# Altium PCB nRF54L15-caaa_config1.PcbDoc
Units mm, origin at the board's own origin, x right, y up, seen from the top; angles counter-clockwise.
Board outline 10.87 x 7.5 mm, 8 copper layers (Top Layer, Mid-Layer 1, Mid-Layer 2, Mid-Layer 3, Mid-Layer 4, Mid-Layer 5, Mid-Layer 6, Bottom Layer), stack 1.547 mm thick; 17 components, 46 nets, 81 pads, 107 vias.
Unrouted connection lines stored in the file: 18.
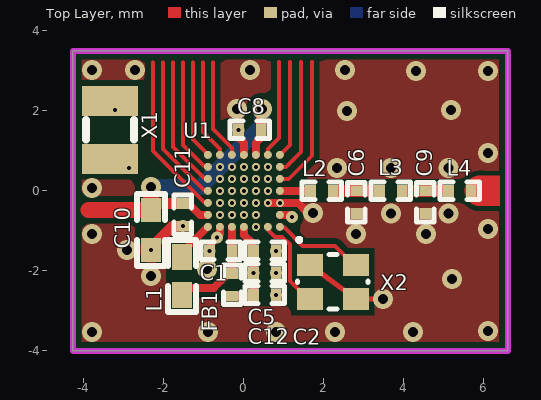
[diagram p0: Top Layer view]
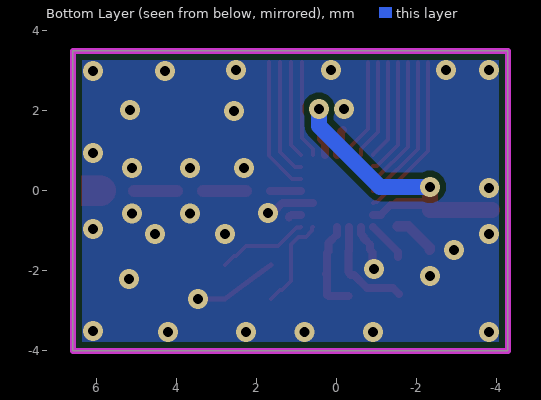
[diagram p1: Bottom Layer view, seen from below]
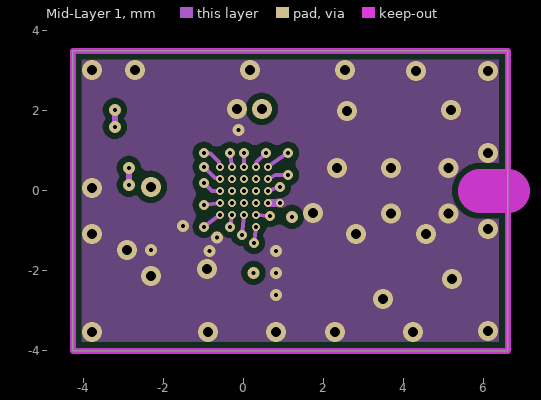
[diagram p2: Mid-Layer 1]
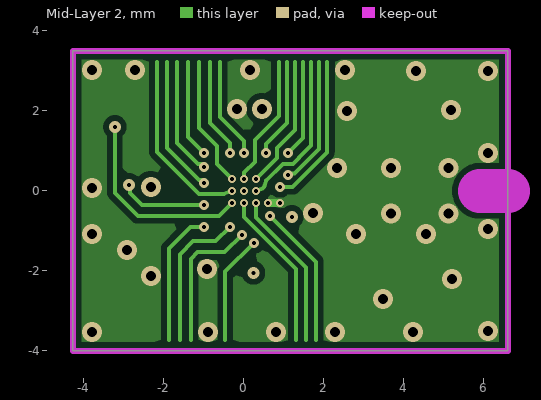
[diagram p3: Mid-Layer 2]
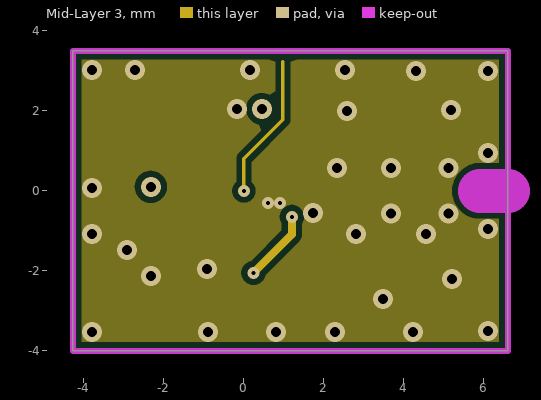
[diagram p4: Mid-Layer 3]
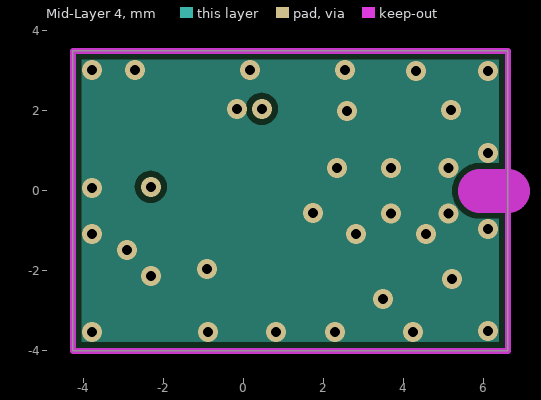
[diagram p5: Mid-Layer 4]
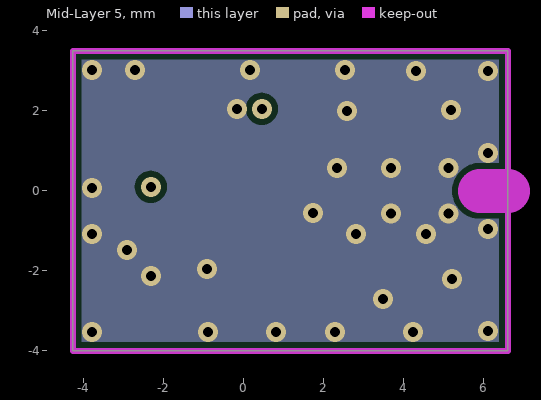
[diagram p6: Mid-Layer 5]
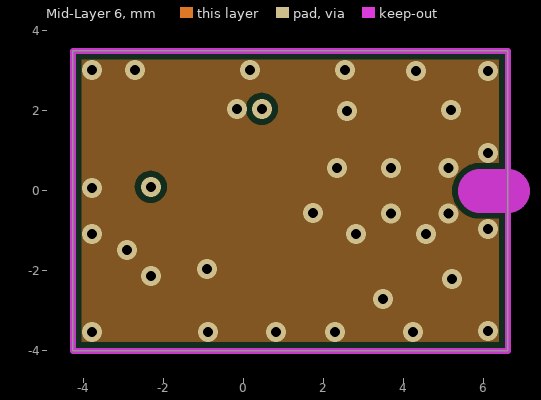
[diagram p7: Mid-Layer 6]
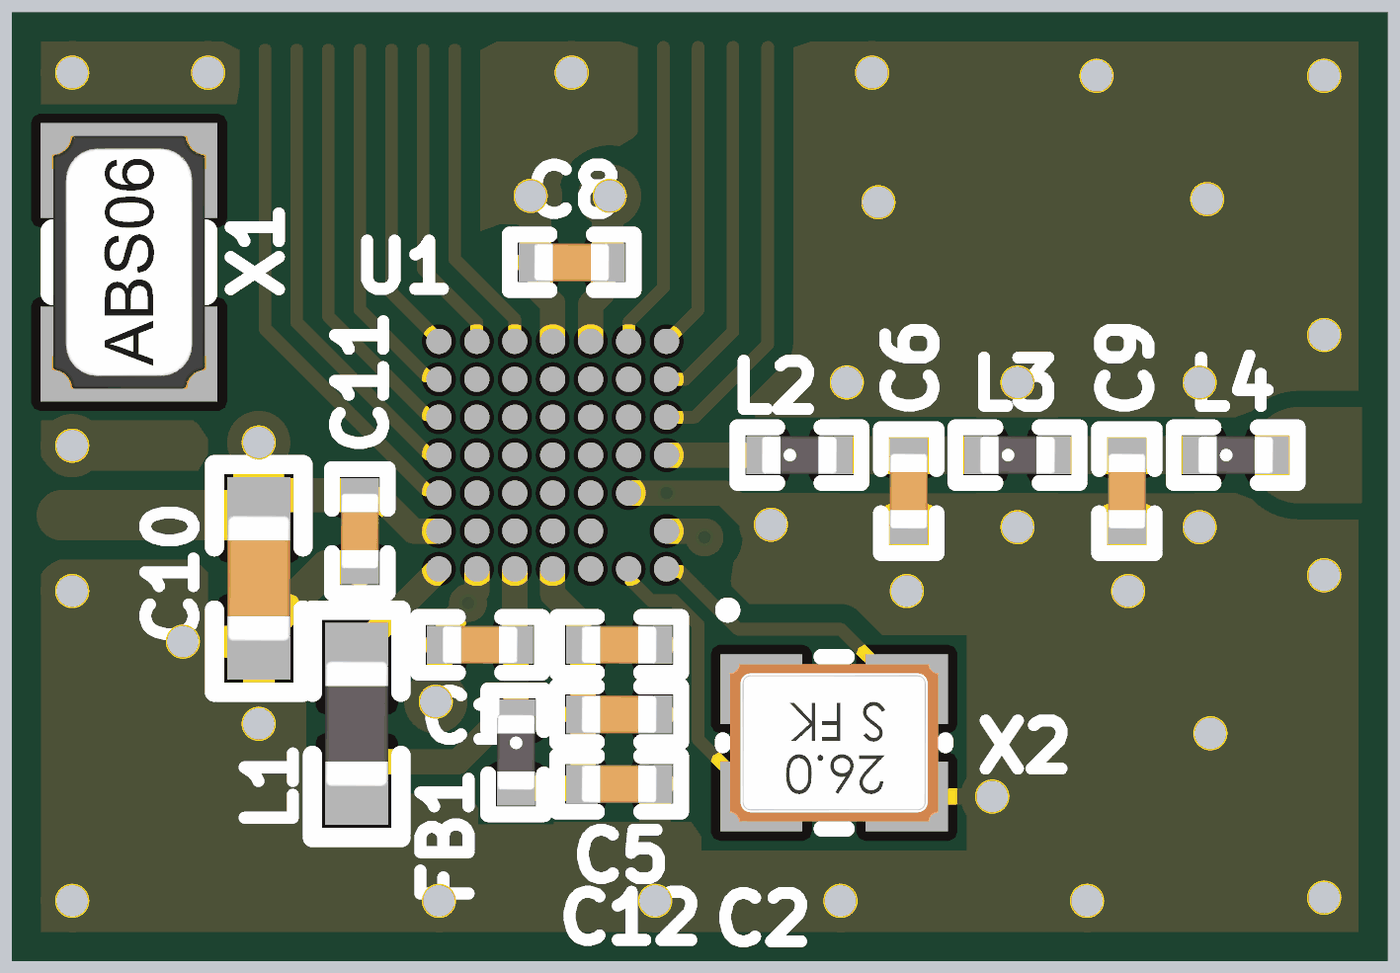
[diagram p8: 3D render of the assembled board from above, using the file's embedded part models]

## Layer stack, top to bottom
Top Solder: solder mask 0.011, Solder Resist, Dk 3.5
Top Layer: signal copper 0.035
Dielectric 1: prepreg 0.08, Dk 4.2
Mid-Layer 1: signal copper 0.035
Dielectric 2: prepreg 0.08, Dk 4.1
Mid-Layer 2: signal copper 0.035
Dielectric 6: prepreg 0.08, Dk 4.1
Mid-Layer 3: signal copper 0.035
Dielectric 3: core 0.7874, Dk 4.6
Mid-Layer 4: signal copper 0.035
Dielectric 7: prepreg 0.08, Dk 4.1
Mid-Layer 5: signal copper 0.035
Dielectric 4: prepreg 0.08, Dk 4.1
Mid-Layer 6: signal copper 0.035
Dielectric 5: prepreg 0.08, Dk 4.2
Bottom Layer: signal copper 0.035
Board Layer Stack Bottom Solder: solder mask 0.011, Solder Resist, Dk 3.5

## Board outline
-4.275,-4 6.6,-4 6.6,3.5 -4.275,3.5

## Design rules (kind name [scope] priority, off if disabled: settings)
Clearance Polygon_ANT [(InNamedPolygon('GND')) or (InNamedPolygon('Bottom_Layer-GND')) or IsRegion vs InNet('RF')] p1: gap=0.127 ignorepadtopadclearanceinfootprint=FALSE
Clearance Clearance_Poly [IsRegion] p2: gap=0.15 ignorepadtopadclearanceinfootprint=FALSE
Clearance [All] p3: gap=0.1 ignorepadtopadclearanceinfootprint=FALSE
ComponentClearance [All] p1 off: gap=0.254 collisioncheckmode=3 verticalgap=0.254 showdistances=FALSE
FabricationTestPointUsage TestPointUsage [All] p1: valid=0 allowmultiple=FALSE
FabricationTestpoint Testpoint [All] p1: side=3 testpointundercomponent=TRUE minsize=1.016 maxsize=2.54 preferedsize=1.524 minholesize=0 maxholesize=1.016 preferedholesize=0.813 testpointgrid=0.025 allowsidetop=TRUE allowsidebottom=TRUE usegrid=TRUE gridtolerance=0
Height [All] p1 off: minheight=0 maxheight=25.4 prefheight=12.7
HoleSize [All] p1: absolutevalues=TRUE maxlimit=4 minlimit=0.1 maxpercent=80.000 minpercent=20.000
HoleToHoleClearance [IsThruVia vs IsThruVia] p1: gap=0.36 allowstackedmicrovias=TRUE
MinimumAnnularRing [All] p1 off: minimumring=0.152
PlaneClearance [All] p1: clearance=0.2
PolygonConnect PolygonConnect_1 [isVia and innet(gnd) or InComponent('C6') or InComponent('C9')] p1: connectstyle=Direct reliefconductorwidth=0.254 reliefentries=4 polygonreliefangle="90 Angle" airgapwidth=0.254
PolygonConnect [All] p2: thpad.connectstyle=Relief thpad.reliefconductorwidth=0.254 thpad.reliefentries=4 thpad.polygonreliefangle="90 Angle" thpad.airgapwidth=0.15 smdpad.connectstyle=Relief smdpad.reliefconductorwidth=0.25 smdpad.reliefentries=4 smdpad.polygonreliefangle="90 Angle" smdpad.airgapwidth=0.15 via.connectstyle=Direct via.reliefconductorwidth=0.254 via.reliefentries=4 via.polygonreliefangle="90 Angle" via.airgapwidth=0.25
RoutingVias [All] p1: holewidth=0.2 width=0.4 viastyle="Through Hole" minholewidth=0.1 minwidth=0.2 maxholewidth=1 maxwidth=2
SilkToSolderMaskClearance SilkscreenOverComponentPads [IsPad] p1: minsilkscreentomaskgap=0.254 clearancetoexposedcopper=TRUE
SolderMaskExpansion SolderMaskExpansion_via [IsVia] p1: expansion=0.102 istentingtop=TRUE
SolderMaskExpansion [All] p2: expansion=0.076 istentingtop=FALSE
SupplyNets "Schematic Supply Nets_1" [InNet('GND')] p1: voltage=0.000
SupplyNets "Schematic Supply Nets" [InNet('VDD_nRF')] p2: voltage=0.000
Width [All] p1: maxlimit=3 minlimit=0.09 preferedwidth=0.15
22 further rules are at their usual default settings.

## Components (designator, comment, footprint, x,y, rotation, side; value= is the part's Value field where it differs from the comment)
C1 "2.2µF" CAPC0603X03L_C -0.575,-1.5 r0 top
C2 "2.2µF" CAPC0603X03L_C 0.525,-2.6 r180 top
C5 "3.9pF" CAPC0603X03L_C 0.525,-1.5 r180 top
C6 "1.7pF" CAPC0603X03L_C 2.815,-0.285 r90 top
C8 "100nF" CAPC0603X03L_C 0.15,1.525 r180 top
C9 "2.0pF" CAPC0603X03L_C 4.54,-0.285 r90 top
C10 "10µF" CAPC1005X04L -2.325,-0.975 r90 top
C11 "100nF" CAPC0603X03L_C -1.525,-0.6 r270 top
C12 "10nF" CAPC0603X03L_C 0.525,-2.05 r180 top
FB1 "120R/0.2A" INDC0603X03L_C -0.29,-2.35 r270 top
L1 "4.7µH" INDC1005X04L -1.55,-2.125 r270 top
L2 "3.6nH" INDC0603X03L_C 1.95,0 r0 top
L3 "4.5nH" INDC0603X03L_C 3.675,0 r0 top
L4 "4.5nH" INDC0603X03L_C 5.4,0 r0 top
U1 "nRF54L15-CAAABB0" BGA49C30P7x7_2245X2451X48 0.084,0 r180 top locked
X1 "32.768kHz" XTAL_2012 -3.35,1.525 r90 top
X2 "32MHz" BT-XTAL_1612 2.225,-2.275 r180 top

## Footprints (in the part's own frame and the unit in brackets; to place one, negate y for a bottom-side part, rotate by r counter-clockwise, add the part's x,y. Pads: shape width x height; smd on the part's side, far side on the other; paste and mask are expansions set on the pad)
BGA49C30P7x7_2245X2451X48 [mm] "BGA/CSP, 47-Leads, Body 0.42x2.451mmx2.245mm, Pitch 0.30mm"
  round 0.2 smd mask+0.035: A1(-0.816,0.9) A2(-0.516,0.9) A3(-0.216,0.9) A4(0.084,0.9) A5(0.384,0.9) A6(0.684,0.9) A7(0.984,0.9) B1(-0.816,0.6) B3(-0.216,0.6) B4(0.084,0.6) B5(0.384,0.6) B6(0.684,0.6) B7(0.984,0.6) C2(-0.516,0.3) C3(-0.216,0.3) C4(0.084,0.3) C5(0.384,0.3) C6(0.684,0.3) C7(0.984,0.3) D1(-0.816,0) D2(-0.516,0) D3(-0.216,0) D4(0.084,0) D5(0.384,0) D6(0.684,0) D7(0.984,0) E1(-0.816,-0.3) E2(-0.516,-0.3) E3(-0.216,-0.3) E4(0.084,-0.3) E5(0.384,-0.3) E6(0.684,-0.3) E7(0.984,-0.3) F1(-0.816,-0.6) F2(-0.516,-0.6) F3(-0.216,-0.6) F4(0.084,-0.6) F5(0.384,-0.6) F6(0.684,-0.6) F7(0.984,-0.6) G1(-0.816,-0.9) G2(-0.516,-0.9) G3(-0.216,-0.9) G4(0.084,-0.9) G5(0.384,-0.9) G6(0.684,-0.9) G7(0.984,-0.9)
  silkscreen extent -1.35,1.18 -1.25,1.27, body extent -1.23,-1.12 1.22,1.12, height 0.42
BT-XTAL_1612 [mm] "Crystal 1.6 x 1.2 mm"
  rect 0.65x0.55 smd: 1(-0.575,-0.425) 2(0.575,-0.425) 3(0.575,0.425) 4(-0.575,0.425)
  silkscreen extent -0.88,-0.68 0.88,0.68, body extent -0.83,-0.63 0.83,0.63, height 0.41
CAPC0603X03L_C [mm] "Chip Capacitor, 2-Leads, Body 0.6x0.3mm, IPC High Density"
  rect 0.27x0.3 smd mask+0.05: 1(-0.285,0) 2(0.285,0)
  silkscreen extent -0.49,-0.22 0.49,0.22, body extent -0.3,-0.15 0.3,0.15, height 0.3
CAPC1005X04L [mm] "Chip Capacitor, 2-Leads, Body 1.0x0.5mm, IPC High Density"
  rect 0.6x0.5 smd: 1(-0.5,0) 2(0.5,0)
  silkscreen extent -0.9,-0.35 0.9,0.35, body extent -0.5,-0.25 0.5,0.25, height 0.5
INDC0603X03L_C [mm] "Chip Inductor, 2-Leads, Body 0.6x0.3mm, IPC High Density"
  rect 0.27x0.3 smd: 1(-0.285,0) 2(0.285,0)
  silkscreen extent -0.49,-0.22 0.49,0.22, body extent -0.3,-0.15 0.3,0.15, height 0.3
INDC1005X04L [mm] "Chip Inductor, 2-Leads, Body 1.0x0.5mm, IPC High Density"
  rect 0.65x0.5 smd: 1(-0.475,0) 2(0.475,0)
  silkscreen extent -0.9,-0.35 0.9,0.35, body extent -0.5,-0.25 0.5,0.25, height 0.5
XTAL_2012 [mm] "XTAL SMD 2.0 x 1.2 mm"
  rect 0.75x1.4 smd: 1(-0.725,0) 2(0.725,0)
  silkscreen extent -0.24,-0.6 0.24,0.6, body extent -1,-0.61 1,0.61, height 0.6

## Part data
C1 C2: library part C0201-2µ2-2.5V-X6T-GRM033D80E225ME47D, "Capacitor, Ceramic, 2.2µF 2.5V X6T 0201,±20%", Manufacturer=Murata, Manufacturer Part Number=GRM033R61A225KE47, Part number IPS=N.A., Part number NEMS=100200527, Supplier Part Number 1=81-GRM033D80E225ME7D
C5: library part C0201-3.9p-HQ-Murata, "Capacitor, NP0, ±0.05pF, 25V", Manufacturer=Murata, Manufacturer Part Number=GJM0333C1E3R9WB01, Part number IPS=N.A., Part number NEMS=100200424
C6: library part C0201-1.7p-25V-NP0-GJM0335C1E1R7WB01, "Capacitor, NP0, ±0.05pF, 25V, High Q", Manufacturer=Murata, Manufacturer Part Number=GJM0335C1E1R7WB01, Part number IPS=N.A., Part number NEMS=100200524, Supplier Part Number 1=GJM0335C1E1R7WB01D-ND
C8 C11: library part C0201-100n-10V-X7R, "Capacitor, X7R, ±10%", Manufacturer=N.A., Part number NEMS=100200469
C9: library part C0201-2.0p-HQ-Murata, "Capacitor, NP0, ±0.05pF, 25V", Manufacturer=Murata, Manufacturer Part Number=GJM0335C1E2R0WB01, Part number IPS=00000001775, Part number NEMS=100200419, Part number Norautron=N.A.
C10: library part C0402-10µF-6.3V-X6S, "Capacitor, X6S, ±20%, 6.3V", Manufacturer=N.A., Part number NEMS=100200478
C12: library part C0201-10n-6.3V-X7R, "Capacitor, X7R, 6.3V", Manufacturer=Murata, Manufacturer Part Number=GRM033R70J103KA01D, Part number IPS=N.A., Part number NEMS=100200407, Supplier Part Number 1=490-1262-1-ND
FB1: library part FB0201-120R@100M-200mA-BLM03AG121SN1D, "Ferrite Bead, 120 Ohm @ 100MHz, 200mA, 500 mOhm Max", Manufacturer=Murata, Manufacturer Part Number=BLM03AG121SN1D, Part number IPS=N.A., Part number NEMS=100300419, Supplier Part Number 1=490-5622-1-ND
L1: library part L0402-4µ7-PLEA67BCA4R7M-1PT00, "Inductor, 300mA, ±20%, 1.08R", Manufacturer="TDK Corporation", Manufacturer Part Number=PLEA67BCA4R7M-1PT00, Part number IPS=N.A., Part number NEMS=100300441, Supplier Part Number 1=445-PLEA67BCA4R7M-1PT00TR-ND
L2: library part L0201-3n6-HQ-Murata, "Inductor, 500mA, ±0.1ｎH, 170mOhm", Manufacturer=Murata, Manufacturer Part Number=LQP03HQ3N6B02, Part number IPS=N.A., Part number NEMS=100300223, Supplier Part Number 1=490-13927-1-ND
L3 L4: library part L0201-4n5-LQP03HQ4N5H02, "Inductor, 400mA, ±3%, 250mOhm", Manufacturer=Murata, Manufacturer Part Number=LQP03HQ4N5H02, Part number IPS=N.A., Supplier Part Number 1=490-LQP03HQ4N5H02DTR-ND
U1: "Multi-protocol Bluetooth Low Energy, IEEE 802.15.4, ANT and 2.4GHz proprietary system-on-chip", Manufacturer="Nordic Semiconductor", Part number IPS=N.A.
X1: library part XTAL_SMD2012_32.768kHz_9pF_TXC, "XTAL SMD 2012, 32.768kHz, 9pF, ±20ppm", Manufacturer="TXC Corporation", Manufacturer Part Number=9HT11-32.768KDZC-T, Part number IPS=N.A., Part number NEMS=101600107, Supplier Part Number 1=887-1426-2-ND
X2: library part XTAL_SMD1612_32MHz_8pF_Kyocera, "XTAL SMD 1612, 32MHz, Cl=8pF, Tot: ±40ppm, Aging: ±1ppm/year", Manufacturer=Kyocera, Manufacturer Part Number=CX1612DB32000D0WZRC3, Part number IPS=N.A., Part number NEMS=101600029

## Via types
v1: diameter 0.5, hole 0.25, Top Layer to Bottom Layer, tented both sides, 34 vias
v2: diameter 0.2, hole 0.1, Top Layer to Mid-Layer 1, tented top, 26 vias
v3: diameter 0.25, hole 0.1, Mid-Layer 1 to Mid-Layer 2, tented top, 17 vias
v4: diameter 0.3, hole 0.1, Top Layer to Mid-Layer 1, tented top, 12 vias
v5: diameter 0.2, hole 0.1, Mid-Layer 1 to Mid-Layer 2, tented top, 11 vias
v6: diameter 0.2/0.3 (per signal layer), hole 0.1, Mid-Layer 2 to Mid-Layer 3, tented top, 3 vias
v7: diameter 0.3, hole 0.1, Mid-Layer 2 to Mid-Layer 3, tented top, 2 vias
v8: diameter 0.3, hole 0.1, Mid-Layer 1 to Mid-Layer 2, 2 vias

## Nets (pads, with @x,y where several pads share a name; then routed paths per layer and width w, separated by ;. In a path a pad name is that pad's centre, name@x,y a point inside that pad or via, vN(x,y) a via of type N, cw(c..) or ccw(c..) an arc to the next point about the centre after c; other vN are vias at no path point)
DCC: L1.1 U1.A7 | length 1
  Top Layer w0.2: L1.1@-1.525,-1.65 -1.525,-1.525 U1.A7
DECA: C2.2 C5.2 C12.2 FB1.2 U1.A4 U1.B1 | length 4.5
  Top Layer w0.2: FB1.2 0.205,-2.635 C2.2 v7(0.24,-2.05) ; U1.A4 0,-1.1 0.205,-1.305 0.205,-1.515 0.24,-1.55 v7(0.24,-2.05) ; C12.2@0.275,-2.085 v7(0.24,-2.05) ; U1.B1 1.136,-0.6 v4@1.2,-0.664 ; v4@1.181,-0.631 v7(1.2,-0.65)
  Mid-Layer 3 w0.2: v7(0.24,-2.05) 1.2,-1.09 v7(1.2,-0.65)
  other v3: 0.24,-2.05 1.2,-0.65
  other v4: 0.24,-2.05 1.2,-0.65
DECD: C1.2 FB1.1 L1.2 U1.A5 | length 2.6
  Top Layer w0.2: L1.2@-1.55,-2.575 -1.4,-2.425 -0.75,-2.425 -0.425,-2.1 -0.34,-2.1 -0.298,-2.058 -0.298,-2.038 -0.29,-2.03 C1.2@-0.29,-1.515 ; U1.A5 -0.3,-1.49 C1.2
GND: C1.1 C2.1 C5.1 C6.1 C8.2 C9.1 C10.1 C11.2 C12.1 U1.A6 U1.C2 U1.G4 X2.2 X2.4 | length 6.9
  Top Layer w0.127: X2.2 1.9,-2.035 2.55,-2.515 X2.4 3.05,-2.7 v1(3.475,-2.7)
  Top Layer w0.2: v1(-0.925,-1.95) -0.892,-1.917 -0.892,-1.537 -0.825,-1.47 -0.825,-1.336 -0.669,-1.18 v4(-0.669,-1.169) ; v4@-0.65,-1.15 v4(-0.669,-1.169) ; U1.A6 -0.6,-1.073 -0.669,-1.142 v4(-0.669,-1.169) ; C8.2@-0.16,1.525 -0.125,1.49 -0.115,1.49 -0.1,1.475 -0.1,1.3 0,1.2 U1.G4 ; v5(0.6,-0.3) v6(0.9,-0.3) 1.355,-0.3 1.57,-0.515 v1@1.725,-0.515
  Top Layer w0.27: v4(-2.325,-1.475) -2.325,-1.425 -1.785,-0.885 v4(-1.525,-0.885)
  Mid-Layer 1 w0.2: v5(0.6,-0.3) v6(0.9,-0.3)
  Mid-Layer 2 w0.2: v5(0.6,-0.3) v6(0.9,-0.3)
  other v1: -3.8,-3.525 -0.9,-3.525 0.81,-3.525 2.275,-3.525 4.225,-3.525 6.1,-3.5 5.2,-2.2 -2.325,-2.125 -2.925,-1.475 -3.8,-1.075 2.8,-1.075 4.55,-1.075 6.1,-0.95 3.675,-0.57 5.115,-0.57 1.725,-0.55 -3.8,0.075 2.325,0.575 3.675,0.575 5.115,0.573 6.1,0.95 2.575,2 5.175,2.025 -0.175,2.05 4.3,3 6.1,3 -3.8,3.025 -2.725,3.025 0.15,3.025 2.525,3.025
  other v2: 0.6,-0.3 0.9,-0.3
  other v4: 0.81,-2.6 0.81,-2.05 -0.86,-1.5 0.81,-1.5 -0.135,1.525
  other v5: 0.9,-0.3
  other v6: 0.6,-0.3
NetC6_2: C6.2 L2.2 L3.1 | length 1.1
  Top Layer w0.3: L2.2@2.275,0 C6.2 L3.1@3.35,0
NetC9_2: C9.2 L3.2 L4.1 | length 1.1
  Top Layer w0.3: L3.2@4,0 C9.2 L4.1@5.075,0
NetL2_1: L2.1 U1.D1 | length 0.8
  Top Layer w0.2: U1.D1 L2.1
NRESET: U1.D2 | length 4.1
  Mid-Layer 1 w0.1: v2(0.6,0) 0.85,0.083 v3(0.9,0.1)
  Mid-Layer 2 w0.1: v3(0.9,0.1) 1.216,0.1 2.075,0.959 2.075,0.975 2.08,0.98 2.08,3.225
P0.00: U1.G1 | length 2.4
  Top Layer w0.1: U1.G1 1.15,1.15 1.15,3.225
P0.01: U1.F1 | length 2.9
  Top Layer w0.1: U1.F1 1.05,0.6 1.425,0.975 1.425,3.225
P0.02: U1.E2 | length 3.7
  Mid-Layer 1 w0.1: v2(0.6,0.3) 0.638,0.319 0.8,0.4 v3(1.1,0.4)
  Mid-Layer 2 w0.1: v3(1.1,0.4) 1.129,0.429 1.262,0.429 1.575,0.742 1.575,0.749 1.875,1.049 1.875,3.225
P0.03: U1.E1 | length 3.4
  Top Layer w0.1: U1.E1 1.122,0.3 1.7,0.878 1.7,3.225
P0.04: U1.D3 | length 4
  Mid-Layer 2 w0.1: v5(0.3,0) 0.47,0.057 0.503,0.09 0.56,0.259 ; 0.56,0.26 0.975,0.675 1.225,0.675 1.375,0.825 1.375,0.831 1.675,1.131 1.675,3.225
  other v2: 0.3,0
P1.00/XL1: U1.C5 X1.2 | length 5.4
  Mid-Layer 1 w0.15: v8(-3.225,1.6) v4(-3.225,2.025)
  Mid-Layer 2 w0.1: v8(-3.225,1.6) -3.225,-0.05 -2.65,-0.625 -0.625,-0.625 v2(-0.3,-0.3)
  other v5: -0.3,-0.3
P1.01/XL2: U1.C6 X1.1 | length 3
  Mid-Layer 1 w0.1: v3@-0.971,-0.321 v3(-1,-0.35) v2(-0.6,-0.3)
  Mid-Layer 1 w0.15: v8(-2.875,0.15) v4(-2.875,0.575)
  Mid-Layer 2 w0.1: v8@-2.85,0.15 -2.85,-0.05 -2.55,-0.35 v3(-1,-0.35)
P1.02/NFC1: U1.C7 | length 4.1
  Top Layer w0.1: -2.275,3.203 -2.275,1 -1,-0.275 -0.939,-0.275 -0.914,-0.3 U1.C7
P1.03/NFC2: U1.D5 | length 4.6
  Mid-Layer 2 w0.1: -2.175,3.225 -2.175,0.975 -1.125,-0.075 -0.5,-0.075 -0.338,-0.014 v5(-0.3,0)
  other v2: -0.3,0
P1.04/AIN0: U1.D6 | length 3.9
  Mid-Layer 1 w0.1: v3(-1,0.2) -0.8,0 v2(-0.6,0)
  Mid-Layer 2 w0.1: -1.925,3.225 -1.925,1.075 -1.125,0.275 v3@-1,0.275 ; v3@-1.041,0.2 v3(-1,0.2)
P1.05/AIN1: U1.E6 | length 3.5
  Mid-Layer 1 w0.1: v3(-1,0.6) -0.719,0.319 -0.619,0.319 v2(-0.6,0.3)
  Mid-Layer 2 w0.1: -1.675,3.225 -1.675,1.2 -1.15,0.675 v3@-1,0.675 ; v3@-1.041,0.6 v3(-1,0.6)
P1.06/AIN2: U1.D7 | length 3.7
  Top Layer w0.1: -2.025,3.203 -2.025,1.05 -0.985,0.01 U1.D7@-0.91,0.01 ; U1.D7@-0.919,0.019 U1.D7
P1.07/AIN3: U1.E7 | length 3.3
  Top Layer w0.1: -1.775,3.203 -1.775,1.1 -0.994,0.319 U1.E7@-0.9,0.319 ; U1.E7@-0.919,0.319 U1.E7
P1.08: U1.F7 | length 2.9
  Top Layer w0.1: -1.525,3.203 -1.525,1.15 -1,0.625 U1.F7@-0.9,0.625
P1.09: U1.B3 | length 3.9
  Mid-Layer 1 w0.1: v2(0.3,-0.6) v3(0.65,-0.625)
  Mid-Layer 2 w0.1: v3(0.65,-0.625) 1.8,-1.775 1.8,-3.732
P1.10: U1.C3 | length 4
  Mid-Layer 2 w0.1: v5(0.3,-0.3) 0.302,-0.302 0.302,-0.666 1.55,-1.914 1.55,-3.732
  other v2: 0.3,-0.3
P1.11: U1.C4 | length 4
  Mid-Layer 2 w0.1: v5(0,-0.3) 0,-0.65 1.3,-1.95 1.3,-3.732
  other v2: 0,-0.3
P1.12: U1.A3 | length 3.1
  Mid-Layer 1 w0.1: v3(0.25,-1.3) v2(0.3,-0.9)
  Mid-Layer 2 w0.1: -0.466,-3.725 -0.466,-2.016 v3(0.25,-1.3)
P1.13: U1.B4 | length 4.1
  Mid-Layer 1 w0.1: v3(-0.05,-1.1) v2(0,-0.6)
  Mid-Layer 2 w0.1: -1.325,-3.725 -1.325,-1.7 -1.158,-1.533 -0.483,-1.533 v3(-0.05,-1.1)
P1.14: U1.B5 | length 4
  Mid-Layer 1 w0.1: v3(-0.35,-0.9) v2(-0.3,-0.6)
  Mid-Layer 2 w0.1: -1.6,-3.725 -1.6,-1.586 -1.272,-1.258 -0.708,-1.258 v3(-0.35,-0.9)
P1.15: U1.B6 | length 3.9
  Mid-Layer 1 w0.1: v3(-1,-0.9) -0.626,-0.619 v2(-0.6,-0.6)
  Mid-Layer 2 w0.1: -1.875,-3.725 -1.875,-1.439 -1.336,-0.9 v3(-1,-0.9)
P2.00: U1.G6 | length 2.5
  Top Layer w0.1: -1.025,3.203 -1.025,1.475 -0.602,1.052 -0.602,0.902 U1.G6
P2.01: U1.G7 | length 2.5
  Top Layer w0.1: -1.275,3.203 -1.275,1.284 -0.9,0.909 U1.G7
P2.02: U1.F6 | length 3
  Mid-Layer 1 w0.1: v3(-1,0.95) -0.981,0.931 -0.831,0.931 -0.619,0.719 -0.619,0.619 v2(-0.6,0.6)
  Mid-Layer 2 w0.1: -1.4,3.225 -1.4,1.35 v3(-1,0.95)
P2.03: U1.E5 | length 3.3
  Mid-Layer 2 w0.1: -1.125,3.225 -1.125,1.575 -0.675,1.125 -0.675,0.675 v5@-0.302,0.302
  other v2: -0.3,0.3
  other v5: -0.3,0.3
P2.04: U1.F5 | length 2.8
  Mid-Layer 1 w0.1: v3(-0.35,0.95) v2(-0.3,0.6)
  Mid-Layer 2 w0.1: -0.85,3.225 -0.85,1.7 -0.35,1.2 v3(-0.35,0.95)
P2.05: U1.G5 | length 2.5
  Top Layer w0.1: -0.775,3.203 -0.775,1.55 -0.301,1.076 U1.G5@-0.301,0.901
P2.06: U1.F4 | length 2.9
  Mid-Layer 1 w0.1: v2(0,0.6) v3(0,0.95)
  Mid-Layer 2 w0.1: -0.6,3.225 -0.6,1.85 0,1.25 v3(0,0.95)
P2.07: U1.E4 | length 3.3
  Mid-Layer 2 w0.1: v5(0,0.3) 0.004,0.304 0.004,0.454 0.275,0.725 0.275,1.275 0.875,1.875 0.875,3.225
  other v2: 0,0.3
P2.08: U1.D4 | length 3.6
  Mid-Layer 3 w0.09: v6(0,0) 0,0.8 0.975,1.775 0.975,3.229
  other v2: 0,0
  other v5: 0,0
P2.09: U1.F3 | length 2.9
  Mid-Layer 1 w0.1: v2(0.3,0.6) 0.319,0.619 0.319,0.719 v3(0.55,0.95)
  Mid-Layer 2 w0.1: v3(0.55,0.95) 0.55,1.175 1.075,1.7 1.075,3.225
P2.10: U1.G2 | length 2.4
  Top Layer w0.1: U1.G2 0.602,0.902 0.602,1.052 0.875,1.325 0.875,3.225
RF: L4.2 | length 0.1
  Top Layer w0.762: 5.9,0 6.01,0
SWDCLK: U1.E3 | length 3.3
  Mid-Layer 2 w0.1: v2(0.3,0.3) 0.825,0.825 0.825,1.075 1.275,1.525 1.275,3.225
  other v5: 0.3,0.3
SWDIO: U1.F2 | length 3
  Mid-Layer 1 w0.1: v2(0.6,0.6) 0.603,0.602 v3(1.1,0.95)
  Mid-Layer 2 w0.1: v3(1.1,0.95) 1.475,1.325 1.475,3.225
VDD_nRF: C8.1 C10.2 C11.1 U1.B7 U1.G3 | length 8.5
  Top Layer w0.2: C11.1@-1.49,-0.35 -1.35,-0.35 -1.1,-0.6 U1.B7 ; U1.G3 0.3,1.192 0.4,1.292 C8.1@0.4,1.525 ; C8.1 C8.1@0.444,1.534 ; v1@0.444,2.044 v1(0.45,2.05)
  Top Layer w0.25: C8.1 v1@0.435,2.035
  Top Layer w0.27: C10.2@-2.165,-0.315 C11.1
  Top Layer w0.4: -3.881,-0.475 C10.2 v1(-2.325,0.1)
  Bottom Layer w0.4: v1(-2.325,0.1) -1.075,0.1 0.45,1.625 v1(0.45,2.05)
XC1: U1.A1 X2.1 | length 2.3
  Top Layer w0.1: U1.A1 0.919,-0.919 1.011,-0.919 1.469,-1.377 2.276,-1.377 2.524,-1.625 2.575,-1.625 X2.1
XC2: U1.A2 X2.3 | length 2.3
  Top Layer w0.1: U1.A2 0.619,-0.919 0.619,-0.994 0.775,-1.15 0.959,-1.15 1.15,-1.341 1.15,-2.25 X2.3@1.375,-2.475 ; X2.3@1.425,-2.475 X2.3

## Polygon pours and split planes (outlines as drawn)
GND on Top Layer "GND" (solid, remove dead copper, pour order 1): -4.275,3.505 -4.275,-3.988 6.6,-3.988 6.6,3.505 3.556,3.505
GND on Bottom Layer "GND" (solid, pour order 2): -4.275,3.505 6.6,3.505 6.6,-3.988 -4.275,-3.988
GND on Mid-Layer 1 "GND" (solid, pour order 3): -4.275,3.505 -4.275,-4 6.6,-4 6.6,3.505 2.464,3.505
GND on Mid-Layer 2 "GND" (solid, pour order 4): -4.275,-4 -4.275,3.5 6.6,3.5 6.6,-4
GND on Mid-Layer 3 "GND" (solid, pour order 5): -4.275,-4 -4.275,3.5 6.6,3.5 6.6,-4
GND on Mid-Layer 4 "GND" (solid, pour order 6): -4.275,-4 -4.275,3.5 6.6,3.5 6.6,-4
GND on Mid-Layer 5 "GND" (solid, pour order 7): -4.275,-4 -4.275,3.5 6.6,3.5 6.6,-4
GND on Mid-Layer 6 "GND" (solid, pour order 8): -4.275,-4 -4.275,3.5 6.6,3.5 6.6,-4

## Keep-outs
Mid-Layer 1:
  lines w1.1: 5.9,0 6.6,0
Mid-Layer 2:
  lines w1.1: 5.9,0 6.6,0
Mid-Layer 6:
  lines w1.1: 5.9,0 6.6,0
Mid-Layer 5:
  lines w1.1: 5.9,0 6.6,0
Mid-Layer 3:
  lines w1.1: 5.9,0 6.6,0
Mid-Layer 4:
  lines w1.1: 5.9,0 6.6,0
Keep-Out Layer:
  the board outline again, w0.152

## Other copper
Top Layer:
  rectangle net RF: 5.95,-0.381 6.4,0.381
  pour cut-out: 0.6,0 1.122,0 1.122,-0.6 0.6,-0.6
  pour cut-out: 1.175,-3.125 3.275,-3.125 3.275,-1.425 1.175,-1.425

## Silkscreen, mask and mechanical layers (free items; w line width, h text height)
Mechanical 1:
  the board outline again, w0.152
